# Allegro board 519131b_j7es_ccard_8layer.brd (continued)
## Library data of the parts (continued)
Y2 Y8 = CRY
Y3 Y6 = CRYSTAL 4-PIN_0
Y5 = CRYSTAL_9
Y7 = CRYSTAL_0

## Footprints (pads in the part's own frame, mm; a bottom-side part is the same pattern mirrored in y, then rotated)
BGA100_1MM
  round 0.508 smd: A1(-4.503,8.006) A2(-3.503,8.006) A9(3.503,8.006) A10(4.503,8.006) B1(-4.503,7.005) B10(4.503,7.005) D2(-3.503,5.004) D3(-2.502,5.004) D4(-1.501,5.004) D5(-0.5,5.004) D6(0.5,5.004) D7(1.501,5.004) D8(2.502,5.004) D9(3.503,5.004) E2(-3.503,4.003) E3(-2.502,4.003) E4(-1.501,4.003) E5(-0.5,4.003) E6(0.5,4.003) E7(1.501,4.003) E8(2.502,4.003) E9(3.503,4.003) F2(-3.503,3.002) F3(-2.502,3.002) F4(-1.501,3.002) F5(-0.5,3.002) F6(0.5,3.002) F7(1.501,3.002) F8(2.502,3.002) F9(3.503,3.002) G2(-3.503,2.002) G3(-2.502,2.002) G4(-1.501,2.002) G5(-0.5,2.002) G6(0.5,2.002) G7(1.501,2.002) G8(2.502,2.002) G9(3.503,2.002) H2(-3.503,1.001) H3(-2.502,1.001) H4(-1.501,1.001) H5(-0.5,1.001) H6(0.5,1.001) H7(1.501,1.001) H8(2.502,1.001) H9(3.503,1.001) J2(-3.503,0) J3(-2.502,0) J4(-1.501,0) J5(-0.5,0) J6(0.5,0) J7(1.501,0) J8(2.502,0) J9(3.503,0) K2(-3.503,-1.001) K3(-2.502,-1.001) K4(-1.501,-1.001) K5(-0.5,-1.001) K6(0.5,-1.001) K7(1.501,-1.001) K8(2.502,-1.001) K9(3.503,-1.001) L2(-3.503,-2.002) L3(-2.502,-2.002) L4(-1.501,-2.002) L5(-0.5,-2.002) L6(0.5,-2.002) L7(1.501,-2.002) L8(2.502,-2.002) L9(3.503,-2.002) M2(-3.503,-3.002) M3(-2.502,-3.002) M4(-1.501,-3.002) M5(-0.5,-3.002) M6(0.5,-3.002) M7(1.501,-3.002) M8(2.502,-3.002) M9(3.503,-3.002) N2(-3.503,-4.003) N3(-2.502,-4.003) N4(-1.501,-4.003) N5(-0.5,-4.003) N6(0.5,-4.003) N7(1.501,-4.003) N8(2.502,-4.003) N9(3.503,-4.003) P2(-3.503,-5.004) P3(-2.502,-5.004) P4(-1.501,-5.004) P5(-0.5,-5.004) P6(0.5,-5.004) P7(1.501,-5.004) P8(2.502,-5.004) P9(3.503,-5.004) T1(-4.503,-7.005) T10(4.503,-7.005) U1(-4.503,-8.006) U2(-3.503,-8.006) U9(3.503,-8.006) U10(4.503,-8.006)
C201-6P6SPC
  rect 0.47x0.381 smd: 1(-0.343,0) 2(0.343,0)
C402-25
  round 0.635 smd: 1(-0.508,0) 2(0.508,0)
C402-25RD
  round 0.635 smd: 1(-0.508,0) 2(0.508,0)
C603-35X45
  oval 0.889x1.143 smd: 1(-0.762,0) 2(0.762,0)
C805-35X60
  oval 0.889x1.524 smd: 1(-0.965,0) 2(0.965,0)
C1206-40X70
  oval 1.016x1.778 smd: 1(-1.524,0) 2(1.524,0)
C1210-70X102
  rect 1.778x3.048 smd: 1(-1.803,0) 2(1.803,0)
CAP0402_0-75
  rect 0.483x0.584 smd: 1(-0.46,0) 2(0.46,0)
CAP0603_1
  rect 0.711x0.889 smd: 1(-0.7,0) 2(0.7,0)
CAP0805_1-5
  rect 1.143x1.448 smd: 1(-0.9,0) 2(0.9,0)
CAP1210_2-75
  rect 1.448x2.794 smd: 1(-1.6,0) 2(1.6,0)
CAP-ELEC-H13
  rect 1.524x5.842 smd: 1(0,4.699) 2(0,-4.699)
CAP-FK-D8-65X117
  rect 1.651x2.972 smd: 1(0,2.261) 2(0,-2.261)
CAPAE_B4CASE
  rect 2.489x1.524 smd: 1(-1.778,0) 2(1.778,0)
CHOKE4-AE2002
  rect 1.27x0.762 smd: 1(-2.349,0.699) 2(-2.349,-0.699) 3(2.349,-0.699) 4(2.349,0.699)
COIL-XAL40
  rect 0.914x3.708 smd: 1(-1.194,0) 2(1.194,0)
COIL-XLF4012
  rect 1.016x3.556 smd: 1(-1.181,0) 2(1.181,0)
CON2-200-250
  rect 1.524x1.524 hole 0.965: 1(0,0)
  round 1.524 hole 0.965: 2(-2.54,0)
CON-2214BR-10G
  rect 1.524x1.524 hole 1.016: 1(0,0)
  round 1.524 hole 1.016: 2(0,7.62) 3(-2.54,0) 4(-2.54,7.62) 5(-5.08,0) 6(-5.08,7.62) 7(-7.62,0) 8(-7.62,7.62) 9(-10.16,0) 10(-10.16,7.62)
CON-1932258
  round 1.118 hole 0.711: 1(-3.5,-0.75) 2(-1,-0.75) 3(1,-0.75) 4(3.5,-0.75) 5(4,0.75) 6(2,0.75) 7(0,0.75) 8(-2,0.75) 9(-4,0.75)
  round 2.921 hole 2.311: G1(-6.57,-2.75) G2(6.57,-2.75)
CON_AV6_STX-4235-3-3_S_R_T_26
  oval 1.854x3.886 hole 1.981x4.013 unplated: (-7,0) (-3,0)
  rect 2.21x2.21 hole 1.524: 1A(0,0)
  round 2.21 hole 1.524: 1B(-10,0) 2A(1.25,7.5) 2B(-10,5) 5A(-11.25,7.5) 5B(0,5)
CON_D4S10E
  round 1.524 hole 0.889: 1(-1.001,1.001) 2(-1.001,-1.001) 3(1.001,-1.001) 4(1.001,1.001)
  oval 2.083x2.794 hole 1.6: SH1(-2.502,2.883) SH2(-2.502,-2.883) SH3(2.502,-2.883) SH4(2.502,2.883)
CON_USB20_472720001_S_R_T_7
  round 1.346 hole 1.473 unplated: (0,-2.939)
  rect 0.305x2.388 smd: 1(5.5,7.341) 2(5,7.341) 3(4.5,7.341) 4(4,7.341) 5(3.5,7.341) 6(3,7.341) 7(2.5,7.341) 8(2,7.341) 9(1.5,7.341) 10(1,7.341) 11(0.5,7.341) 12(0,7.341) 13(-0.5,7.341) 14(-1,7.341) 15(-1.5,7.341) 16(-2,7.341) 17(-2.5,7.341) 18(-3,7.341) 19(-3.5,7.341) 20(-4,7.341)
  oval 1.346x2.997 hole 0.66x2.286: SH1(-8.25,4.741) SH2(8.25,4.741)
  oval 1.346x2.489 hole 0.66x1.778: SH3(-8.25,-2.039) SH4(8.25,-2.039)
CONN-1725656
  round 1.2 hole 1.2 unplated: (-1.27,-1.54) (1.27,-1.54)
  rect 1.95x1.95 hole 1.3: 1(1.27,1)
  round 1.95 hole 1.3: 2(-1.27,1)
CONN-1725711
  rect 2.032x2.032 hole 1.092: 1(0,0)
  round 2.032 hole 1.092: 2(2.54,0) 3(5.08,0) 4(7.62,0) 5(10.16,0) 6(12.7,0) 7(15.24,0) 8(17.78,0)
CONN-ST-FAKRA
  round 2.032 hole 1.295: 1(0,0)
  round 2.286 hole 1.473: 2(-2.54,2.54) 3(2.54,2.54) 4(-2.54,-2.54) 5(2.54,-2.54)
DBV6-27X39-6
  rect 0.686x0.991 smd: 1(-0.95,-1.321) 2(0,-1.321) 3(0.95,-1.321) 4(0.95,1.321) 5(0,1.321) 6(-0.95,1.321)
DBV-20X60-5
  rect 0.508x1.524 smd: 1(-0.95,-1.499) 2(0,-1.499) 3(0.95,-1.499) 4(0.95,1.499) 5(-0.95,1.499)
DCK-5
  rect 0.46x0.66 smd: 1(-0.65,-0.991) 2(0,-0.991) 3(0.65,-0.991) 4(0.65,0.991) 5(-0.65,0.991)
DDA8-PAD
  oval 0.635x1.905 smd: 1(-1.905,-2.794) 2(-0.635,-2.794) 3(0.635,-2.794) 4(1.905,-2.794) 5(1.905,2.794) 6(0.635,2.794) 7(-0.635,2.794) 8(-1.905,2.794)
  rect 3.099x2.286 smd: 9(0,0)
DDV44
  rect 0.33x1.473 smd: 1(-6.668,-3.75) 2(-6.032,-3.75) 3(-5.397,-3.75) 4(-4.763,-3.75) 5(-4.128,-3.75) 6(-3.493,-3.75) 7(-2.857,-3.75) 8(-2.223,-3.75) 9(-1.587,-3.75) 10(-0.953,-3.75) 11(-0.318,-3.75) 12(0.318,-3.75) 13(0.953,-3.75) 14(1.587,-3.75) 15(2.223,-3.75) 16(2.857,-3.75) 17(3.493,-3.75) 18(4.128,-3.75) 19(4.763,-3.75) 20(5.397,-3.75) 21(6.032,-3.75) 22(6.668,-3.75) 23(6.668,3.75) 24(6.032,3.75) 25(5.397,3.75) 26(4.763,3.75) 27(4.128,3.75) 28(3.493,3.75) 29(2.857,3.75) 30(2.223,3.75) 31(1.587,3.75) 32(0.953,3.75) 33(0.318,3.75) 34(-0.318,3.75) 35(-0.953,3.75) 36(-1.587,3.75) 37(-2.223,3.75) 38(-2.857,3.75) 39(-3.493,3.75) 40(-4.128,3.75) 41(-4.763,3.75) 42(-5.397,3.75) 43(-6.032,3.75) 44(-6.668,3.75)
DFN5_NTMFS4835N_240X200_1-1
  rect 0.991x0.762 smd: 1(-2.795,1.905) 2(-2.795,0.635) 3(-2.795,-0.635) 4(-2.795,-1.905)
  custom 1.132x1.132 smd: 5(0.935,0)
DIO_SOD323_1-1
  rect 0.914x0.508 smd: 1(-1.25,0) 2(1.25,0)
DPY
  rect 0.61x0.508 smd: 1(-0.495,0) 2(0.495,0)
DQA-PSON10
  rect 0.305x0.762 smd: 1(-1,-0.487) 2(-0.5,-0.487) 4(0.5,-0.487) 5(1,-0.487) 6(1,0.487) 7(0.5,0.487) 9(-0.5,0.487) 10(-1,0.487)
  rect 0.406x0.762 smd: 3(0,-0.487) 8(0,0.487)
DRC10-11X33
  rect 0.305x0.762 smd: 1(-1.001,-1.473) 2(-0.5,-1.473) 3(0,-1.473) 4(0.5,-1.473) 5(1.001,-1.473) 6(1.001,1.473) 7(0.5,1.473) 8(0,1.473) 9(-0.5,1.473) 10(-1.001,1.473)
  custom 0.406x0.406 smd: 11(0,0)
DRL5-12X40
  rect 0.305x1.016 smd: 1(-0.5,-0.813) 2(0,-0.813) 3(0.5,-0.813) 4(0.5,0.813) 5(-0.5,0.813)
DRV6-12X30
  rect 0.305x0.762 smd: 1(-0.65,-1.016) 2(0,-1.016) 3(0.65,-1.016) 4(0.65,1.016) 5(0,1.016) 6(-0.65,1.016)
  rect 1.397x0.889 smd: 7(0,0)
DSG8-11X20
  rect 0.279x0.508 smd: 1(-0.75,-0.965) 2(-0.25,-0.965) 3(0.25,-0.965) 4(0.75,-0.965) 5(0.75,0.965) 6(0.25,0.965) 7(-0.25,0.965) 8(-0.75,0.965)
  rect 1.6x0.889 smd: 9(0,0)
EMI-36X15-DLW21
  rect 0.914x0.381 smd: 1(-0.838,0.406) 2(0.838,0.406) 3(0.838,-0.406) 4(-0.838,-0.406)
EMI-36X15-DLW21-RDPADS
  oval 0.914x0.381 smd: 1(-0.838,0.406) 2(0.838,0.406) 3(0.838,-0.406) 4(-0.838,-0.406)
EMI-NFM21P
  rect 0.889x0.813 smd: 1(-1.118,0) 3(1.118,0)
  rect 0.508x2.007 smd: 2(0,0)
EMIFIL_BLM18A_0603
  rect 0.991x0.991 smd: 1(-0.75,0) 2(0.75,0)
EMIFIL_NFM15CC_0402_0-5
  rect 0.305x0.305 smd: 1(-0.5,0) 3(0.5,0)
  rect 0.254x0.762 smd: 2(0,0)
ESD402
  rect 0.889x0.711 smd: 1(-0.635,0) 2(0.635,0)
FCBGA827_31-49_950X950_2-8
  round 0.457 smd: A1(-11.2,11.2) A2(-10.4,11.2) A3(-9.6,11.2) A4(-8.8,11.2) A5(-8,11.2) A6(-7.2,11.2) A7(-6.4,11.2) A8(-5.6,11.2) A9(-4.8,11.2) A10(-4,11.2) A11(-3.2,11.2) A12(-2.4,11.2) A13(-1.6,11.2) A14(-0.8,11.2) A15(0,11.2) A16(0.8,11.2) A17(1.6,11.2) A18(2.4,11.2) A19(3.2,11.2) A20(4,11.2) A21(4.8,11.2) A22(5.6,11.2) A23(6.4,11.2) A24(7.2,11.2) A25(8,11.2) A26(8.8,11.2) A27(9.6,11.2) A28(10.4,11.2) AA1(-11.2,-4.8) AA2(-10.4,-4.8) AA3(-9.6,-4.8) AA4(-8.8,-4.8) AA5(-8,-4.8) AA6(-7.2,-4.8) AA7(-6.4,-4.8) AA8(-5.6,-4.8) AA9(-4.8,-4.8) AA10(-4,-4.8) AA11(-3.2,-4.8) AA12(-2.4,-4.8) AA13(-1.6,-4.8) AA14(-0.8,-4.8) AA15(0,-4.8) AA16(0.8,-4.8) AA17(1.6,-4.8) AA18(2.4,-4.8) AA19(3.2,-4.8) AA20(4,-4.8) AA21(4.8,-4.8) AA22(5.6,-4.8) AA23(6.4,-4.8) AA24(7.2,-4.8) AA25(8,-4.8) AA26(8.8,-4.8) AA27(9.6,-4.8) AA28(10.4,-4.8) AA29(11.2,-4.8) AB1(-11.2,-5.6) AB2(-10.4,-5.6) AB3(-9.6,-5.6) AB4(-8.8,-5.6) AB5(-8,-5.6) AB6(-7.2,-5.6) AB7(-6.4,-5.6) AB8(-5.6,-5.6) AB9(-4.8,-5.6) AB10(-4,-5.6) AB11(-3.2,-5.6) AB12(-2.4,-5.6) AB13(-1.6,-5.6) AB14(-0.8,-5.6) AB15(0,-5.6) AB16(0.8,-5.6) AB17(1.6,-5.6) AB18(2.4,-5.6) AB19(3.2,-5.6) AB20(4,-5.6) AB21(4.8,-5.6) AB22(5.6,-5.6) AB23(6.4,-5.6) AB24(7.2,-5.6) AB25(8,-5.6) AB26(8.8,-5.6) AB27(9.6,-5.6) AB28(10.4,-5.6) AB29(11.2,-5.6) AC1(-11.2,-6.4) AC2(-10.4,-6.4) AC3(-9.6,-6.4) AC4(-8.8,-6.4) AC5(-8,-6.4) AC6(-7.2,-6.4) AC7(-6.4,-6.4) AC8(-5.6,-6.4) AC9(-4.8,-6.4) AC10(-4,-6.4) AC11(-3.2,-6.4) AC12(-2.4,-6.4) AC13(-1.6,-6.4) AC14(-0.8,-6.4) AC15(0,-6.4) AC16(0.8,-6.4) AC17(1.6,-6.4) AC18(2.4,-6.4) AC19(3.2,-6.4) AC20(4,-6.4) AC21(4.8,-6.4) AC22(5.6,-6.4) AC23(6.4,-6.4) AC24(7.2,-6.4) AC25(8,-6.4) AC26(8.8,-6.4) AC27(9.6,-6.4) AC28(10.4,-6.4) AC29(11.2,-6.4) AD1(-11.2,-7.2) AD2(-10.4,-7.2) AD3(-9.6,-7.2) AD4(-8.8,-7.2) AD5(-8,-7.2) AD6(-7.2,-7.2) AD7(-6.4,-7.2) AD8(-5.6,-7.2) AD9(-4.8,-7.2) AD10(-4,-7.2) AD11(-3.2,-7.2) AD12(-2.4,-7.2) AD13(-1.6,-7.2) AD14(-0.8,-7.2) AD15(0,-7.2) AD16(0.8,-7.2) AD17(1.6,-7.2) AD18(2.4,-7.2) AD19(3.2,-7.2) AD20(4,-7.2) AD21(4.8,-7.2) AD22(5.6,-7.2) AD23(6.4,-7.2) AD24(7.2,-7.2) AD25(8,-7.2) AD26(8.8,-7.2) AD27(9.6,-7.2) AD28(10.4,-7.2) AD29(11.2,-7.2) AE1(-11.2,-8) AE2(-10.4,-8) AE3(-9.6,-8) AE4(-8.8,-8) AE5(-8,-8) AE6(-7.2,-8) AE7(-6.4,-8) AE8(-5.6,-8) AE9(-4.8,-8) AE10(-4,-8) AE11(-3.2,-8) AE12(-2.4,-8) AE13(-1.6,-8) AE14(-0.8,-8) AE15(0,-8) AE16(0.8,-8) AE17(1.6,-8) AE18(2.4,-8) AE19(3.2,-8) AE20(4,-8) AE21(4.8,-8) AE22(5.6,-8) AE23(6.4,-8) AE24(7.2,-8) AE25(8,-8) AE26(8.8,-8) AE27(9.6,-8) AE28(10.4,-8) AE29(11.2,-8) AF1(-11.2,-8.8) AF2(-10.4,-8.8) AF3(-9.6,-8.8) AF4(-8.8,-8.8) AF5(-8,-8.8) AF6(-7.2,-8.8) AF7(-6.4,-8.8) AF8(-5.6,-8.8) AF9(-4.8,-8.8) AF10(-4,-8.8) AF11(-3.2,-8.8) AF12(-2.4,-8.8) AF13(-1.6,-8.8) AF14(-0.8,-8.8) AF15(0,-8.8) AF16(0.8,-8.8) AF17(1.6,-8.8) AF18(2.4,-8.8) AF19(3.2,-8.8) AF20(4,-8.8) AF21(4.8,-8.8) AF22(5.6,-8.8) AF23(6.4,-8.8) AF24(7.2,-8.8) AF25(8,-8.8) AF26(8.8,-8.8) AF27(9.6,-8.8) AF28(10.4,-8.8) AF29(11.2,-8.8) AG1(-11.2,-9.6) AG2(-10.4,-9.6) AG3(-9.6,-9.6) AG4(-8.8,-9.6) AG5(-8,-9.6) AG6(-7.2,-9.6) AG7(-6.4,-9.6) AG8(-5.6,-9.6) AG9(-4.8,-9.6) AG10(-4,-9.6) AG11(-3.2,-9.6) AG12(-2.4,-9.6) AG13(-1.6,-9.6) AG14(-0.8,-9.6) AG15(0,-9.6) AG16(0.8,-9.6) AG17(1.6,-9.6) AG18(2.4,-9.6) AG19(3.2,-9.6) AG20(4,-9.6) AG21(4.8,-9.6) AG22(5.6,-9.6) AG23(6.4,-9.6) AG24(7.2,-9.6) AG25(8,-9.6) AG26(8.8,-9.6) AG27(9.6,-9.6) AG28(10.4,-9.6) AG29(11.2,-9.6) AH1(-11.2,-10.4) AH2(-10.4,-10.4) AH3(-9.6,-10.4) AH4(-8.8,-10.4) AH5(-8,-10.4) AH6(-7.2,-10.4) AH7(-6.4,-10.4) AH8(-5.6,-10.4) AH9(-4.8,-10.4) AH10(-4,-10.4) AH11(-3.2,-10.4) AH12(-2.4,-10.4) AH13(-1.6,-10.4) AH14(-0.8,-10.4) AH15(0,-10.4) AH16(0.8,-10.4) AH17(1.6,-10.4) AH18(2.4,-10.4) AH19(3.2,-10.4) AH20(4,-10.4) AH21(4.8,-10.4) AH22(5.6,-10.4) AH23(6.4,-10.4) AH24(7.2,-10.4) AH25(8,-10.4) AH26(8.8,-10.4) AH27(9.6,-10.4) AH28(10.4,-10.4) AH29(11.2,-10.4) AJ2(-10.4,-11.2) AJ3(-9.6,-11.2) AJ4(-8.8,-11.2) AJ5(-8,-11.2) AJ6(-7.2,-11.2) AJ7(-6.4,-11.2) AJ8(-5.6,-11.2) AJ9(-4.8,-11.2) AJ10(-4,-11.2) AJ11(-3.2,-11.2) AJ12(-2.4,-11.2) AJ13(-1.6,-11.2) AJ14(-0.8,-11.2) AJ15(0,-11.2) AJ16(0.8,-11.2) AJ17(1.6,-11.2) AJ18(2.4,-11.2) AJ19(3.2,-11.2) AJ20(4,-11.2) AJ21(4.8,-11.2) AJ22(5.6,-11.2) AJ23(6.4,-11.2) AJ24(7.2,-11.2) AJ25(8,-11.2) AJ26(8.8,-11.2) AJ27(9.6,-11.2) AJ28(10.4,-11.2) AJ29(11.2,-11.2) B1(-11.2,10.4) B2(-10.4,10.4) B3(-9.6,10.4) B4(-8.8,10.4) B5(-8,10.4) B6(-7.2,10.4) B7(-6.4,10.4) B8(-5.6,10.4) B9(-4.8,10.4) B10(-4,10.4) B11(-3.2,10.4) B12(-2.4,10.4) B13(-1.6,10.4) B14(-0.8,10.4) B15(0,10.4) B16(0.8,10.4) B17(1.6,10.4) B18(2.4,10.4) B19(3.2,10.4) B20(4,10.4) B21(4.8,10.4) B22(5.6,10.4) B23(6.4,10.4) B24(7.2,10.4) B25(8,10.4) B26(8.8,10.4) B27(9.6,10.4) B28(10.4,10.4) B29(11.2,10.4) C1(-11.2,9.6) C2(-10.4,9.6) C3(-9.6,9.6) C4(-8.8,9.6) C5(-8,9.6) C6(-7.2,9.6) C7(-6.4,9.6) C8(-5.6,9.6) C9(-4.8,9.6) C10(-4,9.6) C11(-3.2,9.6) C12(-2.4,9.6) C13(-1.6,9.6) C14(-0.8,9.6) C15(0,9.6) C16(0.8,9.6) C17(1.6,9.6) C18(2.4,9.6) C19(3.2,9.6) C20(4,9.6) C21(4.8,9.6) C22(5.6,9.6) C23(6.4,9.6) C24(7.2,9.6) C25(8,9.6) C26(8.8,9.6) C27(9.6,9.6) C28(10.4,9.6) C29(11.2,9.6) D1(-11.2,8.8) D2(-10.4,8.8) D3(-9.6,8.8) D4(-8.8,8.8) D5(-8,8.8) D6(-7.2,8.8) D7(-6.4,8.8) D8(-5.6,8.8) D9(-4.8,8.8) D10(-4,8.8) D11(-3.2,8.8) D12(-2.4,8.8) D13(-1.6,8.8) D14(-0.8,8.8) D15(0,8.8) D16(0.8,8.8) D17(1.6,8.8) D18(2.4,8.8) D19(3.2,8.8) D20(4,8.8) D21(4.8,8.8) D22(5.6,8.8) D23(6.4,8.8) D24(7.2,8.8) D25(8,8.8) D26(8.8,8.8) D27(9.6,8.8) D28(10.4,8.8) D29(11.2,8.8) E1(-11.2,8) E2(-10.4,8) E3(-9.6,8) E4(-8.8,8) E5(-8,8) E6(-7.2,8) E7(-6.4,8) E8(-5.6,8) E9(-4.8,8) E10(-4,8) E11(-3.2,8) E12(-2.4,8) E13(-1.6,8) E14(-0.8,8) E15(0,8) E16(0.8,8) E17(1.6,8) E18(2.4,8) E19(3.2,8) E20(4,8) E21(4.8,8) E22(5.6,8) E23(6.4,8) E24(7.2,8) E25(8,8) E26(8.8,8) E27(9.6,8) E28(10.4,8) E29(11.2,8) F1(-11.2,7.2) F2(-10.4,7.2) F3(-9.6,7.2) F4(-8.8,7.2) F5(-8,7.2) F6(-7.2,7.2) F7(-6.4,7.2) F8(-5.6,7.2) F9(-4.8,7.2) F10(-4,7.2) F11(-3.2,7.2) F12(-2.4,7.2) F13(-1.6,7.2) F14(-0.8,7.2) F15(0,7.2) F16(0.8,7.2) F17(1.6,7.2) F18(2.4,7.2) F19(3.2,7.2) F20(4,7.2) F21(4.8,7.2) F22(5.6,7.2) F23(6.4,7.2) F24(7.2,7.2) F25(8,7.2) F26(8.8,7.2) F27(9.6,7.2) F28(10.4,7.2) F29(11.2,7.2) G1(-11.2,6.4) G2(-10.4,6.4) G3(-9.6,6.4) G4(-8.8,6.4) G5(-8,6.4) G6(-7.2,6.4) G7(-6.4,6.4) G8(-5.6,6.4) G9(-4.8,6.4) G10(-4,6.4) G11(-3.2,6.4) G12(-2.4,6.4) G13(-1.6,6.4) G14(-0.8,6.4) G15(0,6.4) G16(0.8,6.4) G17(1.6,6.4) G18(2.4,6.4) G19(3.2,6.4) G20(4,6.4) G21(4.8,6.4) G22(5.6,6.4) G23(6.4,6.4) G24(7.2,6.4) G25(8,6.4) G26(8.8,6.4) G27(9.6,6.4) G28(10.4,6.4) G29(11.2,6.4) H1(-11.2,5.6) H2(-10.4,5.6) H3(-9.6,5.6) H4(-8.8,5.6) H5(-8,5.6) H6(-7.2,5.6) H7(-6.4,5.6) H8(-5.6,5.6) H9(-4.8,5.6) H10(-4,5.6) H11(-3.2,5.6) H12(-2.4,5.6) H13(-1.6,5.6) H14(-0.8,5.6) H15(0,5.6) H16(0.8,5.6) H17(1.6,5.6) H18(2.4,5.6) H19(3.2,5.6) H20(4,5.6) H21(4.8,5.6) H22(5.6,5.6) H23(6.4,5.6) H24(7.2,5.6) H25(8,5.6) H26(8.8,5.6) H27(9.6,5.6) H28(10.4,5.6) H29(11.2,5.6) J1(-11.2,4.8) J2(-10.4,4.8) J3(-9.6,4.8) J4(-8.8,4.8) J5(-8,4.8) J6(-7.2,4.8) J7(-6.4,4.8) J8(-5.6,4.8) J9(-4.8,4.8) J10(-4,4.8) J11(-3.2,4.8) J12(-2.4,4.8) J13(-1.6,4.8) J14(-0.8,4.8) J15(0,4.8) J16(0.8,4.8) J17(1.6,4.8) J18(2.4,4.8) J19(3.2,4.8) J20(4,4.8) J21(4.8,4.8) J22(5.6,4.8) J23(6.4,4.8) J24(7.2,4.8) J25(8,4.8) J26(8.8,4.8) J27(9.6,4.8) J28(10.4,4.8) J29(11.2,4.8) K1(-11.2,4) K2(-10.4,4) K3(-9.6,4) K4(-8.8,4) K5(-8,4) K6(-7.2,4) K7(-6.4,4) K8(-5.6,4) K9(-4.8,4) K10(-4,4) K11(-3.2,4) K12(-2.4,4) K13(-1.6,4) K14(-0.8,4) K15(0,4) K16(0.8,4) K17(1.6,4) K18(2.4,4) K19(3.2,4) K20(4,4) K21(4.8,4) K22(5.6,4) K23(6.4,4) K24(7.2,4) K25(8,4) K26(8.8,4) K27(9.6,4) K28(10.4,4) K29(11.2,4) L1(-11.2,3.2) L2(-10.4,3.2) L3(-9.6,3.2) L4(-8.8,3.2) L5(-8,3.2) L6(-7.2,3.2) L7(-6.4,3.2) L8(-5.6,3.2) L9(-4.8,3.2) L10(-4,3.2) L11(-3.2,3.2) L12(-2.4,3.2) L13(-1.6,3.2) L14(-0.8,3.2) L15(0,3.2) L16(0.8,3.2) L17(1.6,3.2) L18(2.4,3.2) L19(3.2,3.2) L20(4,3.2) L21(4.8,3.2) L22(5.6,3.2) L23(6.4,3.2) L24(7.2,3.2) L25(8,3.2) L26(8.8,3.2) L27(9.6,3.2) L28(10.4,3.2) L29(11.2,3.2) M1(-11.2,2.4) M2(-10.4,2.4) M3(-9.6,2.4) M4(-8.8,2.4) M5(-8,2.4) M6(-7.2,2.4) M7(-6.4,2.4) M8(-5.6,2.4) M9(-4.8,2.4) M10(-4,2.4) M14(-0.8,2.4) M15(0,2.4) M16(0.8,2.4) M17(1.6,2.4) M18(2.4,2.4) M19(3.2,2.4) M20(4,2.4) M21(4.8,2.4) M22(5.6,2.4) M23(6.4,2.4) M24(7.2,2.4) M25(8,2.4) M26(8.8,2.4) M27(9.6,2.4) M28(10.4,2.4) M29(11.2,2.4) N1(-11.2,1.6) N2(-10.4,1.6) N3(-9.6,1.6) N4(-8.8,1.6) N5(-8,1.6) N6(-7.2,1.6) N7(-6.4,1.6) N8(-5.6,1.6) N9(-4.8,1.6) N10(-4,1.6) N14(-0.8,1.6) N15(0,1.6) N16(0.8,1.6) N17(1.6,1.6) N18(2.4,1.6) N19(3.2,1.6) N20(4,1.6) N21(4.8,1.6) N22(5.6,1.6) N23(6.4,1.6) N24(7.2,1.6) N25(8,1.6) N26(8.8,1.6) N27(9.6,1.6) N28(10.4,1.6) N29(11.2,1.6) P1(-11.2,0.8) P2(-10.4,0.8) P3(-9.6,0.8) P4(-8.8,0.8) P5(-8,0.8) P6(-7.2,0.8) P7(-6.4,0.8) P8(-5.6,0.8) P9(-4.8,0.8) P10(-4,0.8) P11(-3.2,0.8) P12(-2.4,0.8) P13(-1.6,0.8) P14(-0.8,0.8) P15(0,0.8) P16(0.8,0.8) P17(1.6,0.8) P18(2.4,0.8) P19(3.2,0.8) P20(4,0.8) P21(4.8,0.8) P22(5.6,0.8) P23(6.4,0.8) P24(7.2,0.8) P25(8,0.8) P26(8.8,0.8) P27(9.6,0.8) P28(10.4,0.8) P29(11.2,0.8) R1(-11.2,0) R2(-10.4,0) R3(-9.6,0) R4(-8.8,0) R5(-8,0) R6(-7.2,0) R7(-6.4,0) R8(-5.6,0) R9(-4.8,0) R10(-4,0) R11(-3.2,0) R12(-2.4,0) R13(-1.6,0) R14(-0.8,0) R15(0,0) R16(0.8,0) R17(1.6,0) R18(2.4,0) R19(3.2,0) R20(4,0) R21(4.8,0) R22(5.6,0) R23(6.4,0) R24(7.2,0) R25(8,0) R26(8.8,0) R27(9.6,0) R28(10.4,0) R29(11.2,0) T1(-11.2,-0.8) T2(-10.4,-0.8) T3(-9.6,-0.8) T4(-8.8,-0.8) T5(-8,-0.8) T6(-7.2,-0.8) T7(-6.4,-0.8) T8(-5.6,-0.8) T9(-4.8,-0.8) T10(-4,-0.8) T14(-0.8,-0.8) T15(0,-0.8) T16(0.8,-0.8) T17(1.6,-0.8) T18(2.4,-0.8) T19(3.2,-0.8) T20(4,-0.8) T21(4.8,-0.8) T22(5.6,-0.8) T23(6.4,-0.8) T24(7.2,-0.8) T25(8,-0.8) T26(8.8,-0.8) T27(9.6,-0.8) T28(10.4,-0.8) T29(11.2,-0.8) U1(-11.2,-1.6) U2(-10.4,-1.6) U3(-9.6,-1.6) U4(-8.8,-1.6) U5(-8,-1.6) U6(-7.2,-1.6) U7(-6.4,-1.6) U8(-5.6,-1.6) U9(-4.8,-1.6) U10(-4,-1.6) U14(-0.8,-1.6) U15(0,-1.6) U16(0.8,-1.6) U17(1.6,-1.6) U18(2.4,-1.6) U19(3.2,-1.6) U20(4,-1.6) U21(4.8,-1.6) U22(5.6,-1.6) U23(6.4,-1.6) U24(7.2,-1.6) U25(8,-1.6) U26(8.8,-1.6) U27(9.6,-1.6) U28(10.4,-1.6) U29(11.2,-1.6) V1(-11.2,-2.4) V2(-10.4,-2.4) V3(-9.6,-2.4) V4(-8.8,-2.4) V5(-8,-2.4) V6(-7.2,-2.4) V7(-6.4,-2.4) V8(-5.6,-2.4) V9(-4.8,-2.4) V10(-4,-2.4) V11(-3.2,-2.4) V12(-2.4,-2.4) V13(-1.6,-2.4) V14(-0.8,-2.4) V15(0,-2.4) V16(0.8,-2.4) V17(1.6,-2.4) V18(2.4,-2.4) V19(3.2,-2.4) V20(4,-2.4) V21(4.8,-2.4) V22(5.6,-2.4) V23(6.4,-2.4) V24(7.2,-2.4) V25(8,-2.4) V26(8.8,-2.4) V27(9.6,-2.4) V28(10.4,-2.4) V29(11.2,-2.4) W1(-11.2,-3.2) W2(-10.4,-3.2) W3(-9.6,-3.2) W4(-8.8,-3.2) W5(-8,-3.2) W6(-7.2,-3.2) W7(-6.4,-3.2) W8(-5.6,-3.2) W9(-4.8,-3.2) W10(-4,-3.2) W11(-3.2,-3.2) W12(-2.4,-3.2) W13(-1.6,-3.2) W14(-0.8,-3.2) W15(0,-3.2) W16(0.8,-3.2) W17(1.6,-3.2) W18(2.4,-3.2) W19(3.2,-3.2) W20(4,-3.2) W21(4.8,-3.2) W22(5.6,-3.2) W23(6.4,-3.2) W24(7.2,-3.2) W25(8,-3.2) W26(8.8,-3.2) W27(9.6,-3.2) W28(10.4,-3.2) W29(11.2,-3.2) Y1(-11.2,-4) Y2(-10.4,-4) Y3(-9.6,-4) Y4(-8.8,-4) Y5(-8,-4) Y6(-7.2,-4) Y7(-6.4,-4) Y8(-5.6,-4) Y9(-4.8,-4) Y10(-4,-4) Y11(-3.2,-4) Y12(-2.4,-4) Y13(-1.6,-4) Y14(-0.8,-4) Y15(0,-4) Y16(0.8,-4) Y17(1.6,-4) Y18(2.4,-4) Y19(3.2,-4) Y20(4,-4) Y21(4.8,-4) Y22(5.6,-4) Y23(6.4,-4) Y24(7.2,-4) Y25(8,-4) Y26(8.8,-4) Y27(9.6,-4) Y28(10.4,-4) Y29(11.2,-4)
FX8-120P-SV1
  round 0.508 hole 1.092 unplated: (-20.091,-1.499)
  round 0.254 hole 0.711 unplated: (20.091,-1.499)
  rect 0.356x1.524 smd: 1(-17.694,-2.7) 2(-17.094,-2.7) 3(-16.495,-2.7) 4(-15.895,-2.7) 5(-15.296,-2.7) 6(-14.696,-2.7) 7(-14.097,-2.7) 8(-13.498,-2.7) 9(-12.898,-2.7) 10(-12.299,-2.7) 11(-11.699,-2.7) 12(-11.1,-2.7) 13(-10.5,-2.7) 14(-9.901,-2.7) 15(-9.301,-2.7) 16(-8.702,-2.7) 17(-8.103,-2.7) 18(-7.503,-2.7) 19(-6.904,-2.7) 20(-6.304,-2.7) 21(-5.69,-2.7) 22(-5.095,-2.7) 23(-4.495,-2.7) 24(-3.895,-2.7) 25(-3.295,-2.7) 26(-2.695,-2.7) 27(-2.095,-2.7) 28(-1.495,-2.7) 29(-0.895,-2.7) 30(-0.295,-2.7) 31(0.305,-2.7) 32(0.905,-2.7) 33(1.505,-2.7) 34(2.105,-2.7) 35(2.705,-2.7) 36(3.305,-2.7) 37(3.907,-2.7) 38(4.506,-2.7) 39(5.105,-2.7) 40(5.705,-2.7) 41(6.304,-2.7) 42(6.904,-2.7) 43(7.503,-2.7) 44(8.103,-2.7) 45(8.702,-2.7) 46(9.301,-2.7) 47(9.901,-2.7) 48(10.5,-2.7) 49(11.1,-2.7) 50(11.699,-2.7) 51(12.299,-2.7) 52(12.898,-2.7) 53(13.498,-2.7) 54(14.097,-2.7) 55(14.696,-2.7) 56(15.296,-2.7) 57(15.895,-2.7) 58(16.495,-2.7) 59(17.094,-2.7) 60(17.694,-2.7) 61(17.694,2.7) 62(17.094,2.7) 63(16.495,2.7) 64(15.895,2.7) 65(15.296,2.7) 66(14.696,2.7) 67(14.097,2.7) 68(13.498,2.7) 69(12.898,2.7) 70(12.299,2.7) 71(11.699,2.7) 72(11.1,2.7) 73(10.5,2.7) 74(9.901,2.7) 75(9.301,2.7) 76(8.702,2.7) 77(8.103,2.7) 78(7.503,2.7) 79(6.904,2.7) 80(6.304,2.7) 81(5.705,2.7) 82(5.105,2.7) 83(4.506,2.7) 84(3.907,2.7) 85(3.305,2.7) 86(2.705,2.7) 87(2.105,2.7) 88(1.505,2.7) 89(0.905,2.7) 90(0.305,2.7) 91(-0.295,2.7) 92(-0.895,2.7) 93(-1.495,2.7) 94(-2.094,2.7) 95(-2.694,2.7) 96(-3.294,2.7) 97(-3.894,2.7) 98(-4.494,2.7) 99(-5.094,2.7) 100(-5.694,2.7) 101(-6.304,2.7) 102(-6.904,2.7) 103(-7.503,2.7) 104(-8.103,2.7) 105(-8.702,2.7) 106(-9.301,2.7) 107(-9.901,2.7) 108(-10.5,2.7) 109(-11.1,2.7) 110(-11.699,2.7) 111(-12.299,2.7) 112(-12.898,2.7) 113(-13.498,2.7) 114(-14.097,2.7) 115(-14.696,2.7) 116(-15.296,2.7) 117(-15.895,2.7) 118(-16.495,2.7) 119(-17.094,2.7) 120(-17.694,2.7)
HPH1-3-4025
  round 1.016 hole 0.635: 1(0,0) 2(1.27,0) 3(2.54,0)
HS-DKQ56
  round 6.35 hole 3.175: 1(0,-16.256) 2(0,16.256)
IC8-CP-USON
  rect 0.254x1.016 smd: 1(-0.75,-1.27) 2(-0.25,-1.27) 3(0.25,-1.27) 4(0.75,-1.27) 5(0.75,1.27) 6(0.25,1.27) 7(-0.25,1.27) 8(-0.75,1.27)
  rect 1.27x0.254 smd: 9(0,0)
IND2-7030D
  rect 2.032x3.81 smd: 1(-2.921,0) 2(2.921,0)
IND2-LQH3N
  rect 1.397x3.048 smd: 1(-1.27,0) 2(1.27,0)
IND603-AISC-25X40
  rect 0.635x1.016 smd: 1(-0.635,0) 2(0.635,0)
IND0805-40X70
  rect 1.016x1.778 smd: 1(-0.889,0) 2(0.889,0)
IND1008_1-2
  rect 1.194x2.21 smd: 1(-1.1,0) 2(1.1,0)
IND1608-27X40
  rect 0.686x0.991 smd: 1(-0.889,0) 2(0.889,0)
IND2520-40X80
  rect 1.016x2.032 smd: 1(-1.118,0) 2(1.118,0)
IND-DFEG10040
  rect 2.997x3.429 smd: 1(-4.445,0) 2(4.445,0)
IND-DFEH12060
  rect 3.454x4.877 smd: 1(-5.4,0) 2(5.4,0)
IND-IHLP2020
  rect 1.778x2.794 smd: 1(-2.413,0) 2(2.413,0)
IND-IHLP5050
  rect 2.921x5.385 smd: 1(-5.588,0) 2(5.588,0)
IND-MSS7341
  rect 2.54x7.112 smd: 1(-2.286,0) 2(2.286,0)
IND_SRP1265A
  rect 3.1x5 smd: 1(-5.55,0) 2(5.55,0)
JMP402-25
  rect 0.635x0.635 smd: 1(-0.508,0)
  round 0.635 smd: 2(0.508,0) 3(1.524,0)
L402-25
  round 0.635 smd: 1(-0.508,0) 2(0.508,0)
L603-35X45
  oval 0.889x1.143 smd: 1(-0.762,0) 2(0.762,0)
L805-35X60
  oval 0.889x1.524 smd: 1(-0.965,0) 2(0.965,0)
LED1206-59X59
  rect 1.499x1.499 smd: 1(-1.753,0) 2(1.753,0)
MHP098-175PIP
  round 4.445 hole 2.489: 1(0,0)
MHP125-250
  round 6.35 hole 3.175: 1(0,0)
MOLEX-34826-0124
  round 1.524 hole 0.991: 1(-7.01,1.295) 2(-5.004,1.295) 3(5.004,1.295) 4(7.01,1.295) 5(-7.01,-0.914) 6(-5.004,-0.914) 7(-2.997,-0.914) 8(-0.991,-0.914) 9(0.991,-0.914) 10(2.997,-0.914) 11(5.004,-0.914) 12(7.01,-0.914)
  round 3.556 hole 2.54: 13(-9.855,0) 14(9.855,0)
MOLEX-67910-0002
  rect 2.311x3.2 smd: (-2.149,-3.5) (27.142,-3.5)
  round 1.016 hole 1.6 unplated: (0,0)
  round 0.508 hole 1.092 unplated: (24.994,0)
  rect 0.508x2.007 smd: 1(0.701,-4.102) 2(1.1,4.102) 3(1.501,-4.102) 4(1.9,4.102) 5(2.301,-4.102) 6(2.7,4.102) 7(3.101,-4.102) 8(3.5,4.102) 9(3.901,-4.102) 10(4.3,4.102) 11(4.702,-4.102) 12(5.1,4.102) 13(5.502,-4.102) 14(5.9,4.102) 15(6.302,-4.102) 16(6.701,4.102) 17(10.3,-4.102) 18(10.701,4.102) 19(11.1,-4.102) 20(11.501,4.102) 21(11.9,-4.102) 22(12.301,4.102) 23(12.7,-4.102) 24(13.101,4.102) 25(13.5,-4.102) 26(13.901,4.102) 27(14.3,-4.102) 28(14.702,4.102) 29(15.1,-4.102) 30(15.502,4.102) 31(15.9,-4.102) 32(16.302,4.102) 33(16.701,-4.102) 34(17.102,4.102) 35(17.501,-4.102) 36(17.902,4.102) 37(18.301,-4.102) 38(18.702,4.102) 39(19.101,-4.102) 40(19.502,4.102) 41(19.901,-4.102) 42(20.302,4.102) 43(20.701,-4.102) 44(21.102,4.102) 45(21.501,-4.102) 46(21.902,4.102) 47(22.301,-4.102) 48(22.703,4.102) 49(23.101,-4.102) 50(23.503,4.102) 51(23.901,-4.102) 52(24.303,4.102)
MOLEX-502774-0891
  rect 0.787x1.778 smd: 1(-2.784,7.366) 2(-1.684,7.366) 3(-0.584,7.366) 4(0.516,7.366) 5(1.615,7.366) 6(2.715,7.366) 7(3.815,7.366) 8(4.915,7.366)
  rect 1.295x1.397 smd: 9(6.985,-1.6)
  rect 1.295x1.245 smd: 10(6.985,5.842)
  rect 1.778x2.032 smd: 11(6.858,-7.417) 12(-6.655,-7.391)
  rect 1.854x1.778 smd: 13(-6.35,7.468) 14(6.452,7.595)
NEO-M8U
  rect 0.787x1.524 smd: 1(-7,-5.88) 2(-5.9,-5.88) 3(-4.801,-5.88) 4(-3.701,-5.88) 5(-2.601,-5.88) 6(-1.501,-5.88) 7(-0.401,-5.88) 8(2.598,-5.88) 9(3.698,-5.88) 10(4.798,-5.88) 11(5.898,-5.88) 12(6.998,-5.88) 13(6.998,5.88) 14(5.898,5.88) 15(4.798,5.88) 16(3.698,5.88) 17(2.598,5.88) 18(-0.401,5.88) 19(-1.501,5.88) 20(-2.601,5.88) 21(-3.701,5.88) 22(-4.801,5.88) 23(-5.9,5.88) 24(-7,5.88)
NFM18HC
  rect 0.914x1.016 smd: 1(-0.965,0) 3(0.965,0)
  rect 0.508x1.397 smd: 2(0,0)
OSC4_ASDMB_100X85_SMD_0-9
  rect 0.66x0.864 smd: 1(-0.825,-0.775) 2(0.825,-0.775) 3(0.825,0.775) 4(-0.825,0.775)
PHOENIX_1868076
  rect 1.951x1.951 hole 1.3: 1(0,0)
  round 1.951 hole 1.3: 2(7.62,0)
PHP48-12X70
  oval 0.305x1.778 smd: 1(-2.748,-4.242) 2(-2.25,-4.242) 3(-1.75,-4.242) 4(-1.25,-4.242) 5(-0.749,-4.242) 6(-0.249,-4.242) 7(0.249,-4.242) 8(0.749,-4.242) 9(1.25,-4.242) 10(1.75,-4.242) 11(2.25,-4.242) 12(2.748,-4.242) 25(2.748,4.242) 26(2.25,4.242) 27(1.75,4.242) 28(1.25,4.242) 29(0.749,4.242) 30(0.249,4.242) 31(-0.249,4.242) 32(-0.749,4.242) 33(-1.25,4.242) 34(-1.75,4.242) 35(-2.25,4.242) 36(-2.748,4.242)
  oval 1.778x0.305 smd: 13(4.242,-2.748) 14(4.242,-2.25) 15(4.242,-1.75) 16(4.242,-1.25) 17(4.242,-0.749) 18(4.242,-0.249) 19(4.242,0.249) 20(4.242,0.749) 21(4.242,1.25) 22(4.242,1.75) 23(4.242,2.25) 24(4.242,2.748) 37(-4.242,2.748) 38(-4.242,2.25) 39(-4.242,1.75) 40(-4.242,1.25) 41(-4.242,0.749) 42(-4.242,0.249) 43(-4.242,-0.249) 44(-4.242,-0.749) 45(-4.242,-1.25) 46(-4.242,-1.75) 47(-4.242,-2.25) 48(-4.242,-2.748)
  rect 5.334x5.334 smd: 49(0,0)
PQFP64PM
  rect 0.305x1.524 smd: 1(-3.734,-5.715) 2(-3.226,-5.715) 3(-2.743,-5.715) 4(-2.235,-5.715) 5(-1.727,-5.715) 6(-1.245,-5.715) 7(-0.737,-5.715) 8(-0.229,-5.715) 9(0.254,-5.715) 10(0.762,-5.715) 11(1.27,-5.715) 12(1.753,-5.715) 13(2.261,-5.715) 14(2.769,-5.715) 15(3.251,-5.715) 16(3.759,-5.715) 33(3.759,5.715) 34(3.251,5.715) 35(2.769,5.715) 36(2.261,5.715) 37(1.753,5.715) 38(1.27,5.715) 39(0.762,5.715) 40(0.254,5.715) 41(-0.229,5.715) 42(-0.737,5.715) 43(-1.245,5.715) 44(-1.727,5.715) 45(-2.235,5.715) 46(-2.743,5.715) 47(-3.226,5.715) 48(-3.734,5.715)
  rect 1.524x0.305 smd: 17(5.715,-3.734) 18(5.715,-3.226) 19(5.715,-2.743) 20(5.715,-2.235) 21(5.715,-1.727) 22(5.715,-1.245) 23(5.715,-0.737) 24(5.715,-0.229) 25(5.715,0.254) 26(5.715,0.762) 27(5.715,1.27) 28(5.715,1.753) 29(5.715,2.261) 30(5.715,2.769) 31(5.715,3.251) 32(5.715,3.759) 49(-5.715,3.759) 50(-5.715,3.251) 51(-5.715,2.769) 52(-5.715,2.261) 53(-5.715,1.753) 54(-5.715,1.27) 55(-5.715,0.762) 56(-5.715,0.254) 57(-5.715,-0.229) 58(-5.715,-0.737) 59(-5.715,-1.245) 60(-5.715,-1.727) 61(-5.715,-2.235) 62(-5.715,-2.743) 63(-5.715,-3.226) 64(-5.715,-3.734)
PWP14-14X70-PAD
  oval 0.356x1.778 smd: 1(-1.951,-2.987) 2(-1.3,-2.987) 3(-0.65,-2.987) 4(0,-2.987) 5(0.65,-2.987) 6(1.3,-2.987) 7(1.951,-2.987) 8(1.951,2.987) 9(1.3,2.987) 10(0.65,2.987) 11(0,2.987) 12(-0.65,2.987) 13(-1.3,2.987) 14(-1.951,2.987)
  rect 3.302x2.794 smd: 15(0,0)
PWP16-14X70-PAD
  oval 0.356x1.778 smd: 1(-2.276,-2.987) 2(-1.626,-2.987) 3(-0.975,-2.987) 4(-0.325,-2.987) 5(0.325,-2.987) 6(0.975,-2.987) 7(1.626,-2.987) 8(2.276,-2.987) 9(2.276,2.987) 10(1.626,2.987) 11(0.975,2.987) 12(0.325,2.987) 13(-0.325,2.987) 14(-0.975,2.987) 15(-1.626,2.987) 16(-2.276,2.987)
  rect 4.572x3.048 smd: 17(0,0)
PWP28-14X70
  oval 0.356x1.778 smd: 1(-4.227,-2.921) 2(-3.576,-2.921) 3(-2.926,-2.921) 4(-2.276,-2.921) 5(-1.626,-2.921) 6(-0.975,-2.921) 7(-0.325,-2.921) 8(0.325,-2.921) 9(0.975,-2.921) 10(1.626,-2.921) 11(2.276,-2.921) 12(2.926,-2.921) 13(3.576,-2.921) 14(4.227,-2.921) 15(4.227,2.921) 16(3.576,2.921) 17(2.926,2.921) 18(2.276,2.921) 19(1.626,2.921) 20(0.975,2.921) 21(0.325,2.921) 22(-0.325,2.921) 23(-0.975,2.921) 24(-1.626,2.921) 25(-2.276,2.921) 26(-2.926,2.921) 27(-3.576,2.921) 28(-4.227,2.921)
  rect 7.62x2.54 smd: 29(0,0)
PWR-Q5A-SLPS319
  rect 0.711x1.397 smd: 1(-1.905,0) 2(-0.635,0) 3(0.635,0) 4(1.905,0)
  custom 1.111x1.111 smd: 5(0,2.781)
QFN64_19-68_360X360_0-9_EP6
  rect 0.838x0.305 smd: 1(-4.5,3.75) 2(-4.5,3.25) 3(-4.5,2.75) 4(-4.5,2.25) 5(-4.5,1.75) 6(-4.5,1.25) 7(-4.5,0.75) 8(-4.5,0.25) 9(-4.5,-0.25) 10(-4.5,-0.75) 11(-4.5,-1.25) 12(-4.5,-1.75) 13(-4.5,-2.25) 14(-4.5,-2.75) 15(-4.5,-3.25) 16(-4.5,-3.75) 33(4.5,-3.75) 34(4.5,-3.25) 35(4.5,-2.75) 36(4.5,-2.25) 37(4.5,-1.75) 38(4.5,-1.25) 39(4.5,-0.75) 40(4.5,-0.25) 41(4.5,0.25) 42(4.5,0.75) 43(4.5,1.25) 44(4.5,1.75) 45(4.5,2.25) 46(4.5,2.75) 47(4.5,3.25) 48(4.5,3.75)
  rect 0.305x0.838 smd: 17(-3.75,-4.5) 18(-3.25,-4.5) 19(-2.75,-4.5) 20(-2.25,-4.5) 21(-1.75,-4.5) 22(-1.25,-4.5) 23(-0.75,-4.5) 24(-0.25,-4.5) 25(0.25,-4.5) 26(0.75,-4.5) 27(1.25,-4.5) 28(1.75,-4.5) 29(2.25,-4.5) 30(2.75,-4.5) 31(3.25,-4.5) 32(3.75,-4.5) 49(3.75,4.5) 50(3.25,4.5) 51(2.75,4.5) 52(2.25,4.5) 53(1.75,4.5) 54(1.25,4.5) 55(0.75,4.5) 56(0.25,4.5) 57(-0.25,4.5) 58(-0.75,4.5) 59(-1.25,4.5) 60(-1.75,4.5) 61(-2.25,4.5) 62(-2.75,4.5) 63(-3.25,4.5) 64(-3.75,4.5)
  rect 5.994x5.994 smd: 65(0,0)
QFN88-12X12
  oval 0.889x0.279 smd: 1(-6,5.25) 2(-6,4.75) 3(-6,4.25) 4(-6,3.75) 5(-6,3.25) 6(-6,2.75) 7(-6,2.25) 8(-6,1.75) 9(-6,1.25) 10(-6,0.75) 11(-6,0.25) 12(-6,-0.25) 13(-6,-0.75) 14(-6,-1.25) 15(-6,-1.75) 16(-6,-2.25) 17(-6,-2.75) 18(-6,-3.25) 19(-6,-3.75) 20(-6,-4.25) 21(-6,-4.75) 22(-6,-5.25) 45(6,-5.25) 46(6,-4.75) 47(6,-4.25) 48(6,-3.75) 49(6,-3.25) 50(6,-2.75) 51(6,-2.25) 52(6,-1.75) 53(6,-1.25) 54(6,-0.75) 55(6,-0.25) 56(6,0.25) 57(6,0.75) 58(6,1.25) 59(6,1.75) 60(6,2.25) 61(6,2.75) 62(6,3.25) 63(6,3.75) 64(6,4.25) 65(6,4.75) 66(6,5.25)
  oval 0.279x0.889 smd: 23(-5.25,-6) 24(-4.75,-6) 25(-4.25,-6) 26(-3.75,-6) 27(-3.25,-6) 28(-2.75,-6) 29(-2.25,-6) 30(-1.75,-6) 31(-1.25,-6) 32(-0.75,-6) 33(-0.25,-6) 34(0.25,-6) 35(0.75,-6) 36(1.25,-6) 37(1.75,-6) 38(2.25,-6) 39(2.75,-6) 40(3.25,-6) 41(3.75,-6) 42(4.25,-6) 43(4.75,-6) 44(5.25,-6) 67(5.25,6) 68(4.75,6) 69(4.25,6) 70(3.75,6) 71(3.25,6) 72(2.75,6) 73(2.25,6) 74(1.75,6) 75(1.25,6) 76(0.75,6) 77(0.25,6) 78(-0.25,6) 79(-0.75,6) 80(-1.25,6) 81(-1.75,6) 82(-2.25,6) 83(-2.75,6) 84(-3.25,6) 85(-3.75,6) 86(-4.25,6) 87(-4.75,6) 88(-5.25,6)
  rect 6.502x6.502 smd: 89(0,0)
QSH-030-01-F
  round 0.508 hole 1.016 unplated: (-10.061,2.667) (10.061,2.667)
  rect 0.279x2.273 smd: 1(-7.249,-2.865) 2(-7.249,2.865) 3(-6.749,-2.865) 4(-6.749,2.865) 5(-6.248,-2.865) 6(-6.248,2.865) 7(-5.748,-2.865) 8(-5.748,2.865) 9(-5.248,-2.865) 10(-5.248,2.865) 11(-4.75,-2.865) 12(-4.75,2.865) 13(-4.249,-2.865) 14(-4.249,2.865) 15(-3.749,-2.865) 16(-3.749,2.865) 17(-3.249,-2.865) 18(-3.249,2.865) 19(-2.748,-2.865) 20(-2.748,2.865) 21(-2.25,-2.865) 22(-2.25,2.865) 23(-1.75,-2.865) 24(-1.75,2.865) 25(-1.25,-2.865) 26(-1.25,2.865) 27(-0.749,-2.865) 28(-0.749,2.865) 29(-0.249,-2.865) 30(-0.249,2.865) 31(0.249,-2.865) 32(0.249,2.865) 33(0.749,-2.865) 34(0.749,2.865) 35(1.25,-2.865) 36(1.25,2.865) 37(1.75,-2.865) 38(1.75,2.865) 39(2.25,-2.865) 40(2.25,2.865) 41(2.748,-2.865) 42(2.748,2.865) 43(3.249,-2.865) 44(3.249,2.865) 45(3.749,-2.865) 46(3.749,2.865) 47(4.249,-2.865) 48(4.249,2.865) 49(4.75,-2.865) 50(4.75,2.865) 51(5.248,-2.865) 52(5.248,2.865) 53(5.748,-2.865) 54(5.748,2.865) 55(6.248,-2.865) 56(6.248,2.865) 57(6.749,-2.865) 58(6.749,2.865) 59(7.249,-2.865) 60(7.249,2.865)
  rect 2.54x0.432 smd: 61(-8.065,0) 64(8.065,0)
  rect 4.699x0.432 smd: 62(-3.175,0) 63(3.175,0)
R201-6P6SPC
  rect 0.47x0.381 smd: 1(-0.343,0) 2(0.343,0)
R201-18P5X15
  rect 0.47x0.381 smd: 1(-0.343,0) 2(0.343,0)
R201PL
  rect 0.47x0.381 smd: 1(-0.343,0) 2(0.343,0)
R402-25
  round 0.635 smd: 1(-0.508,0) 2(0.508,0)
R603-35X45
  oval 0.889x1.143 smd: 1(-0.762,0) 2(0.762,0)
R0612
  rect 3.175x0.889 smd: 1(0,-0.813) 2(0,0.813)
R1206-40X70
  oval 1.016x1.778 smd: 1(-1.524,0) 2(1.524,0)
RES0402_0-5
  rect 0.483x0.508 smd: 1(-0.42,0) 2(0.42,0)
RGE24-11X28-4MM
  rect 0.711x0.279 smd: 1(-1.905,1.245) 2(-1.905,0.747) 3(-1.905,0.249) 4(-1.905,-0.249) 5(-1.905,-0.747) 6(-1.905,-1.245) 13(1.905,-1.245) 14(1.905,-0.747) 15(1.905,-0.249) 16(1.905,0.249) 17(1.905,0.747) 18(1.905,1.245)
  rect 0.279x0.711 smd: 7(-1.245,-1.905) 8(-0.747,-1.905) 9(-0.249,-1.905) 10(0.249,-1.905) 11(0.747,-1.905) 12(1.245,-1.905) 19(1.245,1.905) 20(0.747,1.905) 21(0.249,1.905) 22(-0.249,1.905) 23(-0.747,1.905) 24(-1.245,1.905)
  rect 2.464x2.464 smd: 25(0,0)
RGT16-12X34
  oval 0.305x0.864 smd: 1(-0.747,-1.626) 4(0.747,-1.626) 9(0.747,1.626) 12(-0.747,1.626)
  rect 0.305x0.864 smd: 2(-0.249,-1.626) 3(0.249,-1.626) 10(0.249,1.626) 11(-0.249,1.626)
  oval 0.864x0.305 smd: 5(1.626,-0.747) 8(1.626,0.747) 13(-1.626,0.747) 16(-1.626,-0.747)
  rect 0.864x0.305 smd: 6(1.626,-0.249) 7(1.626,0.249) 14(-1.626,0.249) 15(-1.626,-0.249)
  rect 1.778x1.778 smd: 17(0,0)
RGY16-12X34
  oval 0.864x0.305 smd: 1(-2.032,-0.749) 8(2.032,-0.749) 9(2.032,0.749) 16(-2.032,0.749)
  oval 0.305x0.864 smd: 2(-1.252,-1.765) 3(-0.752,-1.765) 4(-0.251,-1.765) 5(0.249,-1.765) 6(0.749,-1.765) 7(1.25,-1.765) 10(1.25,1.765) 11(0.749,1.765) 12(0.249,1.765) 13(-0.251,1.765) 14(-0.752,1.765) 15(-1.252,1.765)
  rect 2.489x2.032 smd: 17(0,0)
RHL24-PVQFN-TI
  rect 0.711x0.305 smd: 1(-2.819,-0.762) 12(2.819,-0.762) 13(2.819,0.762) 24(-2.819,0.762)
  rect 0.305x0.711 smd: 2(-2.25,-1.829) 3(-1.75,-1.829) 4(-1.25,-1.829) 5(-0.749,-1.829) 6(-0.249,-1.829) 7(0.249,-1.829) 8(0.749,-1.829) 9(1.25,-1.829) 10(1.75,-1.829) 11(2.25,-1.829) 14(2.25,1.829) 15(1.75,1.829) 16(1.25,1.829) 17(0.749,1.829) 18(0.249,1.829) 19(-0.249,1.829) 20(-0.749,1.829) 21(-1.25,1.829) 22(-1.75,1.829) 23(-2.25,1.829)
  custom 0.508x0.508 smd: 25(0,0)
RND36-24X10
  oval 0.254x0.61 smd: 1(-2.002,-2.896) 2(-1.501,-2.896) 3(-1.001,-2.896) 4(-0.5,-2.896) 5(0,-2.896) 6(0.498,-2.896) 7(0.998,-2.896) 8(1.499,-2.896) 9(1.999,-2.896) 19(2.002,2.896) 20(1.501,2.896) 21(1.001,2.896) 22(0.5,2.896) 23(0,2.896) 24(-0.498,2.896) 25(-0.998,2.896) 26(-1.499,2.896) 27(-1.999,2.896)
  oval 0.61x0.254 smd: 10(2.896,-2.002) 11(2.896,-1.501) 12(2.896,-1.001) 13(2.896,-0.5) 14(2.896,0) 15(2.896,0.498) 16(2.896,0.998) 17(2.896,1.499) 18(2.896,1.999) 28(-2.896,1.999) 29(-2.896,1.499) 30(-2.896,0.998) 31(-2.896,0.498) 32(-2.896,0) 33(-2.896,-0.5) 34(-2.896,-1.001) 35(-2.896,-1.501) 36(-2.896,-2.002)
  rect 3.81x3.81 smd: 37(0,0)
RTD0064F
  rect 0.6x0.25 smd: 1(-4.4,3.75) 2(-4.4,3.25) 3(-4.4,2.75) 4(-4.4,2.25) 5(-4.4,1.75) 6(-4.4,1.25) 7(-4.4,0.75) 8(-4.4,0.25) 9(-4.4,-0.25) 10(-4.4,-0.75) 11(-4.4,-1.25) 12(-4.4,-1.75) 13(-4.4,-2.25) 14(-4.4,-2.75) 15(-4.4,-3.25) 16(-4.4,-3.75) 33(4.4,-3.75) 34(4.4,-3.25) 35(4.4,-2.75) 36(4.4,-2.25) 37(4.4,-1.75) 38(4.4,-1.25) 39(4.4,-0.75) 40(4.4,-0.25) 41(4.4,0.25) 42(4.4,0.75) 43(4.4,1.25) 44(4.4,1.75) 45(4.4,2.25) 46(4.4,2.75) 47(4.4,3.25) 48(4.4,3.75)
  rect 0.25x0.6 smd: 17(-3.75,-4.4) 18(-3.25,-4.4) 19(-2.75,-4.4) 20(-2.25,-4.4) 21(-1.75,-4.4) 22(-1.25,-4.4) 23(-0.75,-4.4) 24(-0.25,-4.4) 25(0.25,-4.4) 26(0.75,-4.4) 27(1.25,-4.4) 28(1.75,-4.4) 29(2.25,-4.4) 30(2.75,-4.4) 31(3.25,-4.4) 32(3.75,-4.4) 49(3.75,4.4) 50(3.25,4.4) 51(2.75,4.4) 52(2.25,4.4) 53(1.75,4.4) 54(1.25,4.4) 55(0.75,4.4) 56(0.25,4.4) 57(-0.25,4.4) 58(-0.75,4.4) 59(-1.25,4.4) 60(-1.75,4.4) 61(-2.25,4.4) 62(-2.75,4.4) 63(-3.25,4.4) 64(-3.75,4.4)
  rect 5.75x5.75 smd: 65(0,0)
RVC20
  rect 0.279x0.711 smd: 1(-1.245,-1.422) 2(-0.747,-1.422) 3(-0.249,-1.422) 4(0.249,-1.422) 5(0.747,-1.422) 6(1.245,-1.422) 11(1.245,1.422) 12(0.747,1.422) 13(0.249,1.422) 14(-0.249,1.422) 15(-0.747,1.422) 16(-1.245,1.422)
  rect 0.711x0.279 smd: 7(1.905,-0.747) 8(1.905,-0.249) 9(1.905,0.249) 10(1.905,0.747) 17(-1.905,0.747) 18(-1.905,0.249) 19(-1.905,-0.249) 20(-1.905,-0.747)
  rect 2.388x1.6 smd: 21(0,0)
SAMTEC-MUSB
  round 0.508 hole 0.889 unplated: (-2.197,-2.591) (2.197,-2.591)
  rect 0.508x2.286 smd: 1(-1.6,0) 2(-0.8,0) 3(0,0) 4(0.8,0) 5(1.6,0)
  rect 2.007x2.489 smd: 6(-4.445,-0.102) 7(4.445,-0.102) 8(-4.445,-5.613) 9(4.445,-5.613)
SMA2-78SQ
  rect 1.981x1.981 smd: 1(-2.007,0) 2(2.007,0)
SMB-UNI
  rect 1.524x2.286 smd: 1(-2.159,0) 2(2.159,0)
SO8-25X75
  oval 0.635x1.905 smd: 1(-1.905,-2.794) 2(-0.635,-2.794) 3(0.635,-2.794) 4(1.905,-2.794) 5(1.905,2.794) 6(0.635,2.794) 7(-0.635,2.794) 8(-1.905,2.794)
SO8-25X75-295
  oval 0.635x2.54 smd: 1(-1.905,-3.086) 2(-0.635,-3.086) 3(0.635,-3.086) 4(1.905,-3.086) 5(1.905,3.086) 6(0.635,3.086) 7(-0.635,3.086) 8(-1.905,3.086)
SO14-25X75
  oval 0.635x1.905 smd: 1(-3.81,-2.794) 2(-2.54,-2.794) 3(-1.27,-2.794) 4(0,-2.794) 5(1.27,-2.794) 6(2.54,-2.794) 7(3.81,-2.794) 8(3.81,2.794) 9(2.54,2.794) 10(1.27,2.794) 11(0,2.794) 12(-1.27,2.794) 13(-2.54,2.794) 14(-3.81,2.794)
SOD323
  rect 1.092x0.508 smd: 1(-1.194,0) 2(1.194,0)
SOD523
  rect 0.762x0.381 smd: 1(0.838,0) 2(-0.838,0)
SOT23-28X44-GSD
  rect 0.711x1.118 smd: D(0,1.067) G(-0.965,-1.067) S(0.965,-1.067)
SOT23-123_1-2
  rect 0.838x0.61 smd: 1(-1.05,0.95) 2(-1.05,-0.95) 3(1.05,0)
SOT363-16X45
  rect 0.406x0.635 smd: 1(-0.65,-0.978) 2(0,-0.978) 3(0.65,-0.978) 4(0.65,0.978) 5(0,0.978) 6(-0.65,0.978)
SSOP-16
  oval 0.356x1.778 smd: 1(-2.223,-2.692) 2(-1.587,-2.692) 3(-0.953,-2.692) 4(-0.318,-2.692) 5(0.318,-2.692) 6(0.953,-2.692) 7(1.587,-2.692) 8(2.223,-2.692) 9(2.223,2.692) 10(1.587,2.692) 11(0.953,2.692) 12(0.318,2.692) 13(-0.318,2.692) 14(-0.953,2.692) 15(-1.587,2.692) 16(-2.223,2.692)
SW2-30X50-TDA
  rect 0.762x1.27 smd: 1(-0.635,-3.81) 2(0.635,-3.81) 3(0.635,3.81) 4(-0.635,3.81)
SW4-7914G
  rect 1.27x1.778 smd: 1(1.27,2.769) 2(1.27,-2.769) 3(-1.27,2.769) 4(-1.27,-2.769)
SW8-30X50
  rect 0.762x1.27 smd: 1(-4.445,-3.81) 2(-3.175,-3.81) 3(-1.905,-3.81) 4(-0.635,-3.81) 5(0.635,-3.81) 6(1.905,-3.81) 7(3.175,-3.81) 8(4.445,-3.81) 9(4.445,3.81) 10(3.175,3.81) 11(1.905,3.81) 12(0.635,3.81) 13(-0.635,3.81) 14(-1.905,3.81) 15(-3.175,3.81) 16(-4.445,3.81)
TP1-70X135
  rect 2.286x3.937 smd: 1(0,0)
TP20
  round 0.508 smd: 1(0,0)
TP40_SMD
  round 1.016 smd: 1(0,0)
TP-18RD8
  round 0.457 hole 0.203: 1(0,0)
TP-20RD10
  round 0.508 hole 0.254: 1(0,0)
TP-30RD13
  round 0.762 hole 0.33: 1(0,0)
TPBGA24_39-37_240X320_1-2
  round 0.356 smd: A2(-1,2) A3(0,2) A4(1,2) A5(2,2) B1(-2,1) B2(-1,1) B3(0,1) B4(1,1) B5(2,1) C1(-2,0) C2(-1,0) C3(0,0) C4(1,0) C5(2,0) D1(-2,-1) D2(-1,-1) D3(0,-1) D4(1,-1) D5(2,-1) E1(-2,-2) E2(-1,-2) E3(0,-2) E4(1,-2) E5(2,-2)
TSDSON8
  custom 0.248x0.248 smd: 1(-0.33,-1.499)
  rect 0.356x1.016 smd: 4(0.978,-1.486)
  custom 0.572x0.572 smd: 5(0,0.673)
unnamed#2
  round 1.27 smd: 1(0,0)
VQFN56_19-68_320X320_0-9_EP6
  rect 0.787x0.305 smd: 1(-4,3.25) 2(-4,2.75) 3(-4,2.25) 4(-4,1.75) 5(-4,1.25) 6(-4,0.75) 7(-4,0.25) 8(-4,-0.25) 9(-4,-0.75) 10(-4,-1.25) 11(-4,-1.75) 12(-4,-2.25) 13(-4,-2.75) 14(-4,-3.25) 29(4,-3.25) 30(4,-2.75) 31(4,-2.25) 32(4,-1.75) 33(4,-1.25) 34(4,-0.75) 35(4,-0.25) 36(4,0.25) 37(4,0.75) 38(4,1.25) 39(4,1.75) 40(4,2.25) 41(4,2.75) 42(4,3.25)
  rect 0.305x0.787 smd: 15(-3.25,-4) 16(-2.75,-4) 17(-2.25,-4) 18(-1.75,-4) 19(-1.25,-4) 20(-0.75,-4) 21(-0.25,-4) 22(0.25,-4) 23(0.75,-4) 24(1.25,-4) 25(1.75,-4) 26(2.25,-4) 27(2.75,-4) 28(3.25,-4) 43(3.25,4) 44(2.75,4) 45(2.25,4) 46(1.75,4) 47(1.25,4) 48(0.75,4) 49(0.25,4) 50(-0.25,4) 51(-0.75,4) 52(-1.25,4) 53(-1.75,4) 54(-2.25,4) 55(-2.75,4) 56(-3.25,4)
  rect 5.588x5.588 smd: 57(0,0)
WFBGA200_MT53DDS_400X570_1
  round 0.356 smd: A1(-4.4,6.825) A2(-3.6,6.825) A3(-2.8,6.825) A4(-2,6.825) A5(-1.2,6.825) A8(1.2,6.825) A9(2,6.825) A10(2.8,6.825) A11(3.6,6.825) A12(4.4,6.825) AA1(-4.4,-6.175) AA2(-3.6,-6.175) AA3(-2.8,-6.175) AA4(-2,-6.175) AA5(-1.2,-6.175) AA8(1.2,-6.175) AA9(2,-6.175) AA10(2.8,-6.175) AA11(3.6,-6.175) AA12(4.4,-6.175) AB1(-4.4,-6.825) AB2(-3.6,-6.825) AB3(-2.8,-6.825) AB4(-2,-6.825) AB5(-1.2,-6.825) AB8(1.2,-6.825) AB9(2,-6.825) AB10(2.8,-6.825) AB11(3.6,-6.825) AB12(4.4,-6.825) B1(-4.4,6.175) B2(-3.6,6.175) B3(-2.8,6.175) B4(-2,6.175) B5(-1.2,6.175) B8(1.2,6.175) B9(2,6.175) B10(2.8,6.175) B11(3.6,6.175) B12(4.4,6.175) C1(-4.4,5.525) C2(-3.6,5.525) C3(-2.8,5.525) C4(-2,5.525) C5(-1.2,5.525) C8(1.2,5.525) C9(2,5.525) C10(2.8,5.525) C11(3.6,5.525) C12(4.4,5.525) D1(-4.4,4.875) D2(-3.6,4.875) D3(-2.8,4.875) D4(-2,4.875) D5(-1.2,4.875) D8(1.2,4.875) D9(2,4.875) D10(2.8,4.875) D11(3.6,4.875) D12(4.4,4.875) E1(-4.4,4.225) E2(-3.6,4.225) E3(-2.8,4.225) E4(-2,4.225) E5(-1.2,4.225) E8(1.2,4.225) E9(2,4.225) E10(2.8,4.225) E11(3.6,4.225) E12(4.4,4.225) F1(-4.4,3.575) F2(-3.6,3.575) F3(-2.8,3.575) F4(-2,3.575) F5(-1.2,3.575) F8(1.2,3.575) F9(2,3.575) F10(2.8,3.575) F11(3.6,3.575) F12(4.4,3.575) G1(-4.4,2.925) G2(-3.6,2.925) G3(-2.8,2.925) G4(-2,2.925) G5(-1.2,2.925) G8(1.2,2.925) G9(2,2.925) G10(2.8,2.925) G11(3.6,2.925) G12(4.4,2.925) H1(-4.4,2.275) H2(-3.6,2.275) H3(-2.8,2.275) H4(-2,2.275) H5(-1.2,2.275) H8(1.2,2.275) H9(2,2.275) H10(2.8,2.275) H11(3.6,2.275) H12(4.4,2.275) J1(-4.4,1.625) J2(-3.6,1.625) J3(-2.8,1.625) J4(-2,1.625) J5(-1.2,1.625) J8(1.2,1.625) J9(2,1.625) J10(2.8,1.625) J11(3.6,1.625) J12(4.4,1.625) K1(-4.4,0.975) K2(-3.6,0.975) K3(-2.8,0.975) K4(-2,0.975) K5(-1.2,0.975) K8(1.2,0.975) K9(2,0.975) K10(2.8,0.975) K11(3.6,0.975) K12(4.4,0.975) N1(-4.4,-0.975) N2(-3.6,-0.975) N3(-2.8,-0.975) N4(-2,-0.975) N5(-1.2,-0.975) N8(1.2,-0.975) N9(2,-0.975) N10(2.8,-0.975) N11(3.6,-0.975) N12(4.4,-0.975) P1(-4.4,-1.625) P2(-3.6,-1.625) P3(-2.8,-1.625) P4(-2,-1.625) P5(-1.2,-1.625) P8(1.2,-1.625) P9(2,-1.625) P10(2.8,-1.625) P11(3.6,-1.625) P12(4.4,-1.625) R1(-4.4,-2.275) R2(-3.6,-2.275) R3(-2.8,-2.275) R4(-2,-2.275) R5(-1.2,-2.275) R8(1.2,-2.275) R9(2,-2.275) R10(2.8,-2.275) R11(3.6,-2.275) R12(4.4,-2.275) T1(-4.4,-2.925) T2(-3.6,-2.925) T3(-2.8,-2.925) T4(-2,-2.925) T5(-1.2,-2.925) T8(1.2,-2.925) T9(2,-2.925) T10(2.8,-2.925) T11(3.6,-2.925) T12(4.4,-2.925) U1(-4.4,-3.575) U2(-3.6,-3.575) U3(-2.8,-3.575) U4(-2,-3.575) U5(-1.2,-3.575) U8(1.2,-3.575) U9(2,-3.575) U10(2.8,-3.575) U11(3.6,-3.575) U12(4.4,-3.575) V1(-4.4,-4.225) V2(-3.6,-4.225) V3(-2.8,-4.225) V4(-2,-4.225) V5(-1.2,-4.225) V8(1.2,-4.225) V9(2,-4.225) V10(2.8,-4.225) V11(3.6,-4.225) V12(4.4,-4.225) W1(-4.4,-4.875) W2(-3.6,-4.875) W3(-2.8,-4.875) W4(-2,-4.875) W5(-1.2,-4.875) W8(1.2,-4.875) W9(2,-4.875) W10(2.8,-4.875) W11(3.6,-4.875) W12(4.4,-4.875) Y1(-4.4,-5.525) Y2(-3.6,-5.525) Y3(-2.8,-5.525) Y4(-2,-5.525) Y5(-1.2,-5.525) Y8(1.2,-5.525) Y9(2,-5.525) Y10(2.8,-5.525) Y11(3.6,-5.525) Y12(4.4,-5.525)
WSON8_19-68_80X80_0-8
  rect 0.711x0.305 smd: 1(-1.05,0.75) 2(-1.05,0.25) 3(-1.05,-0.25) 4(-1.05,-0.75) 5(1.05,-0.75) 6(1.05,-0.25) 7(1.05,0.25) 8(1.05,0.75)
  rect 0.991x1.702 smd: 9(0,0)
XTAL2-75X94
  rect 1.905x2.413 smd: 1(-2.235,0) 2(2.235,0)
XTAL4-55X47-3225
  rect 1.397x1.194 smd: 1(-1.092,-0.838) 2(1.092,-0.838) 3(1.092,0.838) 4(-1.092,0.838)
XTAL4-63X50-ECX53B
  rect 1.6x1.27 smd: 1(-1.854,-1.092) 2(1.854,-1.092) 3(1.854,1.092) 4(-1.854,1.092)
XTAL4-ABM11
  rect 0.889x0.813 smd: 1(-0.711,-0.559) 2(0.711,-0.559) 3(0.711,0.559) 4(-0.711,0.559)
XTAL4_ABM10W_100X80_SMD_0-6
  rect 1.194x0.838 smd: 1(-0.813,-0.6) 2(0.813,-0.6) 3(0.813,0.6) 4(-0.813,0.6)
XTAL4_S3225A_135X110_SMD_0-8
  rect 1.295x1.041 smd: 1(-1.15,-0.925) 2(1.15,-0.925) 3(1.15,0.925) 4(-1.15,0.925)
XTAL_ECS-32_130X60_SMD_0-9
  rect 1.118x1.905 smd: 1(-1.25,0) 2(1.25,0)

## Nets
